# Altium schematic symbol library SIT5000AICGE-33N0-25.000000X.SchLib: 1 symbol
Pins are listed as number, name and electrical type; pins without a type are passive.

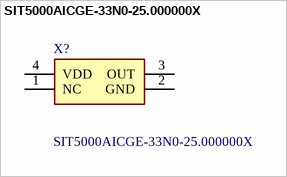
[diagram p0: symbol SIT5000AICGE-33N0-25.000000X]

## SIT5000AICGE-33N0-25.000000X
designator X?
TCXO Oscillators 25MHz 3.3V -40C +85C 5ppm; Manufacturer_Name: SiTime; Geometry.Height: 0.8mm
footprint SIT5000AICGE33N025000000X
pins: 1 NC, 2 GND, 3 OUT, 4 VDD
